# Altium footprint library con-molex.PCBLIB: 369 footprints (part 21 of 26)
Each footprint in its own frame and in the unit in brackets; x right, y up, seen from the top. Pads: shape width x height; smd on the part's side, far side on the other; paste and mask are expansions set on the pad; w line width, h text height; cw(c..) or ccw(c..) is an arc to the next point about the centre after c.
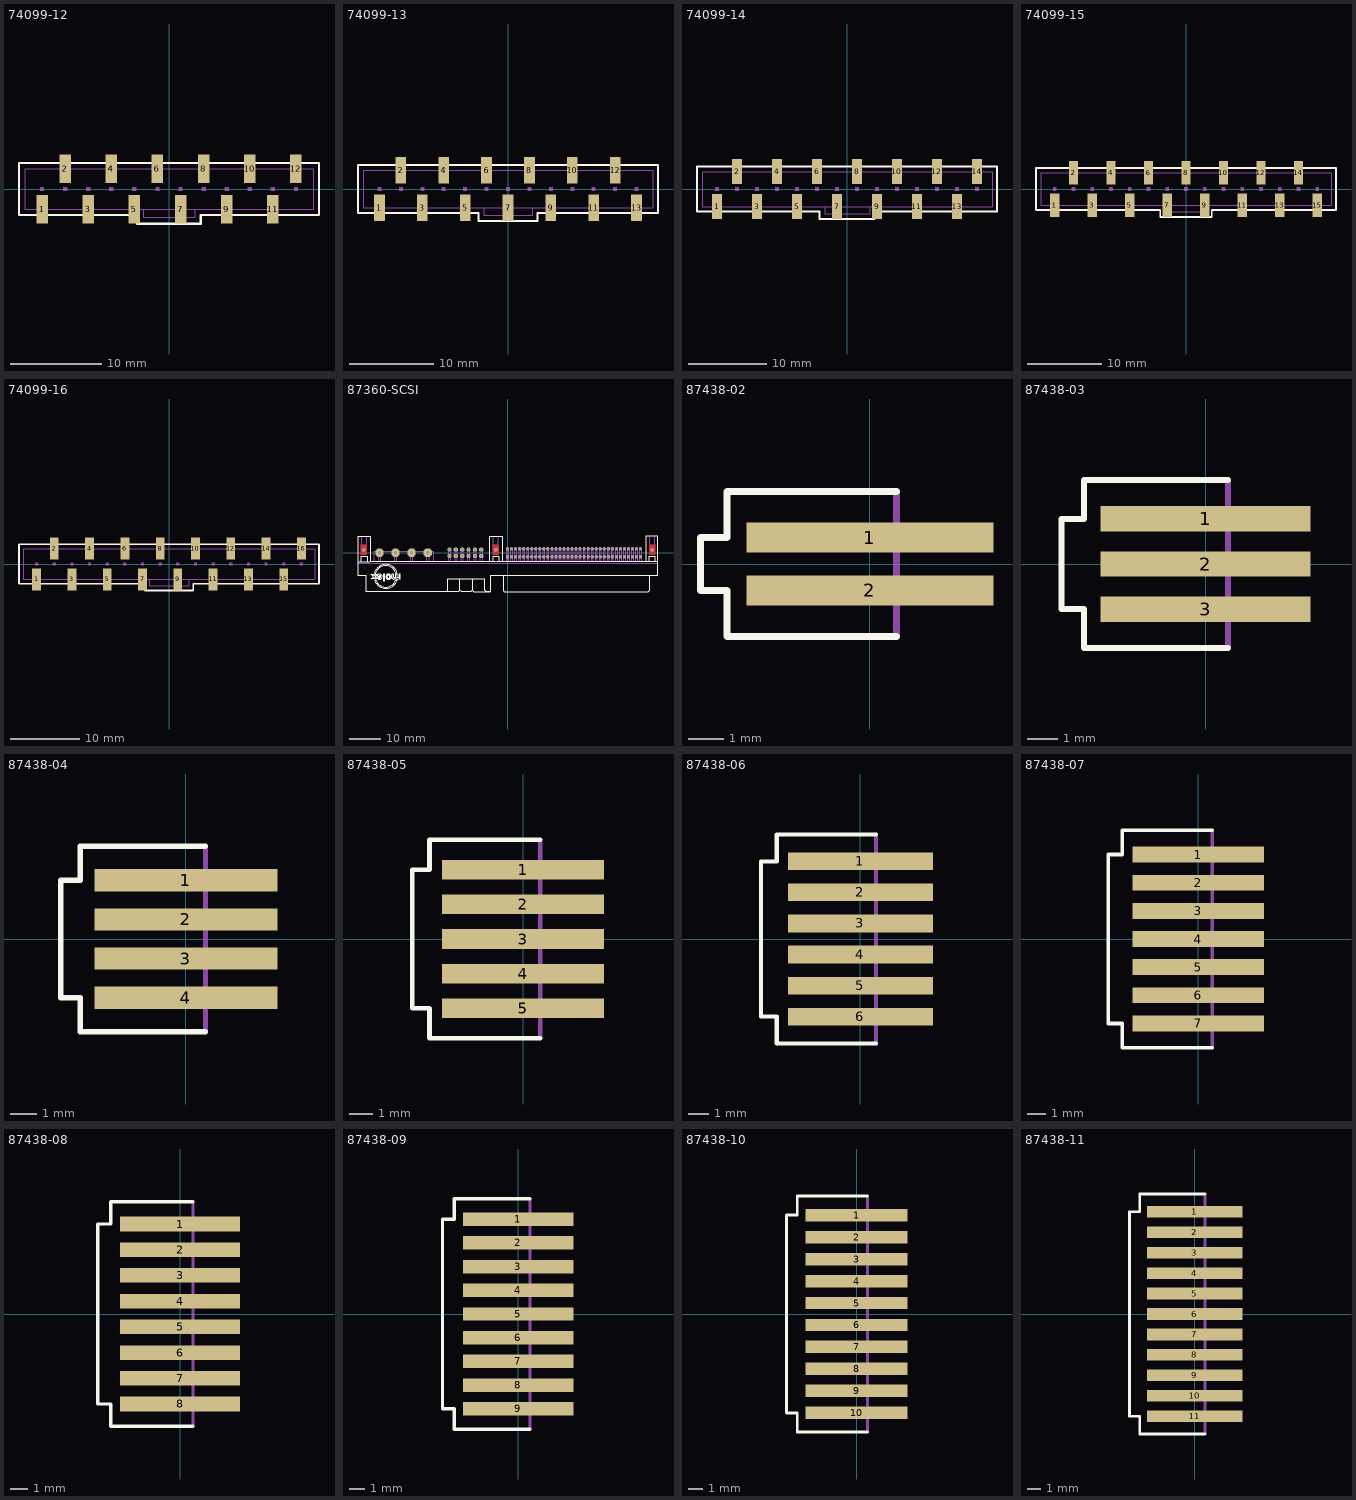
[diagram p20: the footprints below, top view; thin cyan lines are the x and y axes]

## 74099-12 [mil]
pads (12):
  rect 50x125 smd: 1(-550,-87.5) 2(-450,87.5) 3(-350,-87.5) 4(-250,87.5) 5(-150,-87.5) 6(-50,87.5) 7(50,-87.5) 8(150,87.5) 9(250,-87.5) 10(350,87.5) 11(450,-87.5) 12(550,87.5)
Top Overlay:
  lines w10: -650,-112.5 -650,112.5 650,112.5 650,-112.5 137.5,-112.5 137.5,-150 -137.5,-150 -137.5,-112.5 -650,-112.5
Mechanical 16:
  rectangle: -359.37,-9.37 -340.63,9.37
  rectangle: -459.37,-9.37 -440.63,9.37
  rectangle: -159.37,-9.37 -140.63,9.37
  rectangle: -259.37,-9.37 -240.63,9.37
  rectangle: -559.37,-9.37 -540.63,9.37
  rectangle: -59.37,-9.37 -40.63,9.37
  rectangle: 40.63,-9.37 59.37,9.37
  rectangle: 140.63,-9.37 159.37,9.37
  rectangle: 240.63,-9.37 259.37,9.37
  rectangle: 340.63,-9.37 359.37,9.37
  rectangle: 440.63,-9.37 459.37,9.37
  rectangle: 540.63,-9.37 559.37,9.37
  lines w2: -112.5,-87.5 -625,-87.5 -625,87.5 625,87.5 625,-87.5 112.5,-87.5 ; -112.5,-87.5 112.5,-87.5 ; -112.5,-87.5 -112.5,-125 112.5,-125 112.5,-87.5
  text "1" at -612.5,-75 h62

## 74099-13 [mil]
pads (13):
  rect 50x125 smd: 1(-600,-87.5) 2(-500,87.5) 3(-400,-87.5) 4(-300,87.5) 5(-200,-87.5) 6(-100,87.5) 7(0,-87.5) 8(100,87.5) 9(200,-87.5) 10(300,87.5) 11(400,-87.5) 12(500,87.5) 13(600,-87.5)
Top Overlay:
  lines w10: -700,-112.5 -700,112.5 700,112.5 700,-112.5 137.5,-112.5 137.5,-150 -137.5,-150 -137.5,-112.5 -700,-112.5
Mechanical 16:
  rectangle: -409.37,-9.37 -390.63,9.37
  rectangle: -509.37,-9.37 -490.63,9.37
  rectangle: -209.37,-9.37 -190.63,9.37
  rectangle: -309.37,-9.37 -290.63,9.37
  rectangle: -609.37,-9.37 -590.63,9.37
  rectangle: -109.37,-9.37 -90.63,9.37
  rectangle: -9.37,-9.37 9.37,9.37
  rectangle: 90.63,-9.37 109.37,9.37
  rectangle: 190.63,-9.37 209.37,9.37
  rectangle: 290.63,-9.37 309.37,9.37
  rectangle: 390.63,-9.37 409.37,9.37
  rectangle: 490.63,-9.37 509.37,9.37
  rectangle: 590.63,-9.37 609.37,9.37
  lines w2: -112.5,-87.5 -675,-87.5 -675,87.5 675,87.5 675,-87.5 112.5,-87.5 ; -112.5,-87.5 112.5,-87.5 ; -112.5,-87.5 -112.5,-125 112.5,-125 112.5,-87.5
  text "1" at -662.5,-75 h62

## 74099-14 [mil]
pads (14):
  rect 50x125 smd: 1(-650,-87.5) 2(-550,87.5) 3(-450,-87.5) 4(-350,87.5) 5(-250,-87.5) 6(-150,87.5) 7(-50,-87.5) 8(50,87.5) 9(150,-87.5) 10(250,87.5) 11(350,-87.5) 12(450,87.5) 13(550,-87.5) 14(650,87.5)
Top Overlay:
  lines w10: -750,-112.5 -750,112.5 750,112.5 750,-112.5 137.5,-112.5 137.5,-150 -137.5,-150 -137.5,-112.5 -750,-112.5
Mechanical 16:
  rectangle: -459.37,-9.37 -440.63,9.37
  rectangle: -559.37,-9.37 -540.63,9.37
  rectangle: -259.37,-9.37 -240.63,9.37
  rectangle: -359.37,-9.37 -340.63,9.37
  rectangle: -659.37,-9.37 -640.63,9.37
  rectangle: -159.37,-9.37 -140.63,9.37
  rectangle: -59.37,-9.37 -40.63,9.37
  rectangle: 40.63,-9.37 59.37,9.37
  rectangle: 140.63,-9.37 159.37,9.37
  rectangle: 240.63,-9.37 259.37,9.37
  rectangle: 340.63,-9.37 359.37,9.37
  rectangle: 440.63,-9.37 459.37,9.37
  rectangle: 540.63,-9.37 559.37,9.37
  rectangle: 640.63,-9.37 659.37,9.37
  lines w2: -112.5,-87.5 -725,-87.5 -725,87.5 725,87.5 725,-87.5 112.5,-87.5 ; -112.5,-87.5 112.5,-87.5 ; -112.5,-87.5 -112.5,-125 112.5,-125 112.5,-87.5
  text "1" at -712.5,-75 h62

## 74099-15 [mil]
pads (15):
  rect 50x125 smd: 1(-700,-87.5) 2(-600,87.5) 3(-500,-87.5) 4(-400,87.5) 5(-300,-87.5) 6(-200,87.5) 7(-100,-87.5) 8(0,87.5) 9(100,-87.5) 10(200,87.5) 11(300,-87.5) 12(400,87.5) 13(500,-87.5) 14(600,87.5) 15(700,-87.5)
Top Overlay:
  lines w10: -800,-112.5 -800,112.5 800,112.5 800,-112.5 137.5,-112.5 137.5,-150 -137.5,-150 -137.5,-112.5 -800,-112.5
Mechanical 16:
  rectangle: -509.37,-9.37 -490.63,9.37
  rectangle: -609.37,-9.37 -590.63,9.37
  rectangle: -309.37,-9.37 -290.63,9.37
  rectangle: -409.37,-9.37 -390.63,9.37
  rectangle: -709.37,-9.37 -690.63,9.37
  rectangle: -209.37,-9.37 -190.63,9.37
  rectangle: -109.37,-9.37 -90.63,9.37
  rectangle: -9.37,-9.37 9.37,9.37
  rectangle: 90.63,-9.37 109.37,9.37
  rectangle: 190.63,-9.37 209.37,9.37
  rectangle: 290.63,-9.37 309.37,9.37
  rectangle: 390.63,-9.37 409.37,9.37
  rectangle: 490.63,-9.37 509.37,9.37
  rectangle: 590.63,-9.37 609.37,9.37
  rectangle: 690.63,-9.37 709.37,9.37
  lines w2: -112.5,-87.5 -775,-87.5 -775,87.5 775,87.5 775,-87.5 112.5,-87.5 ; -112.5,-87.5 112.5,-87.5 ; -112.5,-87.5 -112.5,-125 112.5,-125 112.5,-87.5
  text "1" at -762.5,-75 h62

## 74099-16 [mil]
pads (16):
  rect 50x125 smd: 1(-750,-87.5) 2(-650,87.5) 3(-550,-87.5) 4(-450,87.5) 5(-350,-87.5) 6(-250,87.5) 7(-150,-87.5) 8(-50,87.5) 9(50,-87.5) 10(150,87.5) 11(250,-87.5) 12(350,87.5) 13(450,-87.5) 14(550,87.5) 15(650,-87.5) 16(750,87.5)
Top Overlay:
  lines w10: -850,-112.5 -850,112.5 850,112.5 850,-112.5 137.5,-112.5 137.5,-150 -137.5,-150 -137.5,-112.5 -850,-112.5
Mechanical 16:
  rectangle: -559.37,-9.37 -540.63,9.37
  rectangle: -659.37,-9.37 -640.63,9.37
  rectangle: -359.37,-9.37 -340.63,9.37
  rectangle: -459.37,-9.37 -440.63,9.37
  rectangle: -759.37,-9.37 -740.63,9.37
  rectangle: -259.37,-9.37 -240.63,9.37
  rectangle: -159.37,-9.37 -140.63,9.37
  rectangle: -59.37,-9.37 -40.63,9.37
  rectangle: 40.63,-9.37 59.37,9.37
  rectangle: 140.63,-9.37 159.37,9.37
  rectangle: 240.63,-9.37 259.37,9.37
  rectangle: 340.63,-9.37 359.37,9.37
  rectangle: 440.63,-9.37 459.37,9.37
  rectangle: 540.63,-9.37 559.37,9.37
  rectangle: 640.63,-9.37 659.37,9.37
  rectangle: 740.63,-9.37 759.37,9.37
  lines w2: -112.5,-87.5 -825,-87.5 -825,87.5 825,87.5 825,-87.5 112.5,-87.5 ; -112.5,-87.5 112.5,-87.5 ; -112.5,-87.5 -112.5,-125 112.5,-125 112.5,-87.5
  text "1" at -812.5,-75 h62

## 87360-SCSI [mil]
pads (87):
  round 44.88 hole 44.88: 1(-1783.27,36.22) 1(-145.08,36.22) 1(1795.08,36.22)
  oct 40x40 hole 27.56: 1(0,50) 2(50,50) 3(100,50) 4(150,50) 5(200,50) 6(250,50) 7(300,50) 8(350,50) 9(400,50) 10(450,50) 11(500,50) 12(550,50) 13(600,50) 14(650,50) 15(700,50) 16(750,50) 17(800,50) 18(850,50) 19(900,50) 20(950,50) 21(1000,50) 22(1050,50) 23(1100,50) 24(1150,50) 25(1200,50) 26(1250,50) 27(1300,50) 28(1350,50) 29(1400,50) 30(1450,50) 31(1500,50) 32(1550,50) 33(1600,50) 34(1650,50) 35(0,-50) 36(50,-50) 37(100,-50) 38(150,-50) 39(200,-50) 40(250,-50) 41(300,-50) 42(350,-50) 43(400,-50) 44(450,-50) 45(500,-50) 46(550,-50) 47(600,-50) 48(650,-50) 49(700,-50) 50(750,-50) 51(800,-50) 52(850,-50) 53(900,-50) 54(950,-50) 55(1000,-50) 56(1050,-50) 57(1100,-50) 58(1150,-50) 59(1200,-50) 60(1250,-50) 61(1300,-50) 62(1350,-50) 63(1400,-50) 64(1450,-50) 65(1500,-50) 66(1550,-50) 67(1600,-50) 68(1650,-50)
  oct 53.15x53.15 hole 35.43: J1(-719.69,39.37) J2(-719.69,-39.37) J3(-640.94,39.37) J4(-640.94,-39.37) J5(-562.2,39.37) J6(-562.2,-39.37) J7(-483.46,39.37) J8(-483.46,-39.37) J9(-404.72,39.37) J10(-404.72,-39.37) J11(-325.98,39.37) J12(-325.98,-39.37)
  oct 100x100 hole 39.37: P1(-1589.76,0) P2(-1389.76,0) P3(-1189.76,0) P4(-989.76,0)
Top Layer:
  rectangle: -1823.23,-26.57 -1743.5,99.41
  rectangle: -184.45,-26.57 -105.71,99.41
  rectangle: 1755.51,-26.57 1834.25,99.41
Bottom Layer:
  rectangle: -1823.23,-26.57 -1743.5,99.41
  rectangle: -184.45,-26.57 -105.71,99.41
  rectangle: 1755.51,-26.57 1834.25,99.41
Top Overlay:
  circle w8: c-1476.94,-297.65 r33.91
  circle w8: c-1476.94,-297.65 r18.84
  lines w8: -1854.33,-130.59 -1854.33,-287.4 ; -1850.39,-110.24 -1708.66,-110.24 ; -1814.96,-106.3 -1814.96,-43.31 -1740.16,-43.31 -1740.16,-106.3 ; -1638.98,-256.22 -1654.02,-256.22 cw(c-1510.32,-293.9) -1367.67,-252.45 ; -1638.96,-259.97 cw(c-1510.86,-293.88) -1382.75,-259.97 ; -1616.34,-293.9 -1571.14,-293.9 -1571.14,-286.34 -1574.92,-282.6 -1593.74,-282.6 -1601.3,-290.12 ; -1397.83,-312.72 -1409.13,-312.72 -1412.91,-308.94 -1412.91,-267.52 -1435.51,-267.52 -1435.51,-312.72 -1420.43,-327.8 -1405.35,-327.8 -1394.06,-316.5 ; -1386.54,-342.87 -1371.46,-342.87 cw(c-1510.23,-293.88) -1650.28,-339.09 -1635.2,-339.09 ccw(c-1510.87,-293.88) -1386.53,-339.09 ; -1382.76,-256.22 -1367.68,-256.22 ; -1356.38,-312.72 -1367.68,-312.72 -1371.46,-308.94 -1371.46,-267.52 -1394.06,-267.52 -1394.06,-312.72 -1378.98,-327.8 -1360.16,-327.8 -1352.6,-320.28 ; -609.13,-484.25 -610.24,-484.25 ; -588.62,-326.77 -439.84,-326.77 ; -456.69,-484.25 -437.01,-464.57 ; -455,-484.25 -570.87,-484.25 -590.55,-464.57 ; -417.32,-484.25 -437.01,-464.57 ; -416.85,-484.25 -212.6,-484.25 ; -181.1,-110.24 -220.47,-110.24 ; -102.36,-110.24 -66.93,-110.24 ; 1718.98,-110.24 1863.46,-110.24 ; 1866.14,-130.59 1866.14,-287.4 ; 1866.14,196.85 1866.14,204.72 ; -1854.33,-287.4 -1755.91,-287.4 ; -1854.33,-287.4 -1755.91,-287.4 ; -1854.33,-287.4 -1854.33,204.72 -1700.79,204.72 -1700.79,-110.24 -220.47,-110.24 ; -1755.91,-484.25 -1755.91,-287.4 ; -1755.91,-484.25 -759.84,-484.25 -748.03,-472.44 -748.03,-326.77 -590.55,-326.77 ; -1755.91,-484.25 -1755.91,-287.4 ; -1755.91,-484.25 -610.24,-484.25 ; -610.24,-484.25 -590.55,-464.57 ; -590.55,-464.57 -590.55,-326.77 ; -590.55,-464.57 -590.55,-326.77 ; -437.01,-464.57 -437.01,-326.77 ; -437.01,-464.57 -437.01,-326.77 ; -437.01,-326.77 -283.46,-326.77 -283.46,-464.57 -263.78,-484.25 -212.6,-484.25 ; -220.47,-110.24 -220.47,204.72 -66.93,204.72 -66.93,-110.24 ; -212.6,-484.25 -212.6,-287.4 ; -212.6,-484.25 -212.6,-287.4 ; -212.6,-287.4 -55.12,-287.4 ; -212.6,-287.4 -55.12,-287.4 ; -66.93,-110.24 1716.54,-110.24 1716.54,204.72 1866.14,204.72 ; -55.12,-468.5 -55.12,-287.4 ; -55.12,-468.5 -39.37,-484.25 ; -55.12,-468.5 -55.12,-287.4 ; -55.12,-468.5 -39.37,-484.25 ; -55.12,-287.4 1755.91,-287.4 ; -55.12,-287.4 1755.91,-287.4 ; -39.37,-484.25 1744.09,-484.25 ; -39.37,-484.25 1744.09,-484.25 ; 1744.09,-484.25 1755.91,-472.44 ; 1744.09,-484.25 1755.91,-472.44 ; 1755.91,-472.44 1755.91,-287.4 ; 1755.91,-472.44 1755.91,-287.4 ; 1755.91,-287.4 1866.14,-287.4 ; 1755.91,-287.4 1866.14,-287.4 ; 1866.14,-287.4 1866.14,204.72 ; -1691.69,-267.52 -1669.09,-267.52 -1654.02,-282.6 -1638.98,-267.52 -1616.34,-267.52 -1642.72,-293.9 -1642.72,-301.42 -1620.12,-324.02 -1642.72,-324.02 -1654.02,-312.72 -1665.31,-324.02 -1687.95,-324.02 -1665.31,-301.42 -1665.31,-293.9 -1691.69,-267.52 ; -1620.12,-301.42 -1620.12,-286.34 -1601.3,-267.52 -1571.14,-267.52 -1556.06,-282.6 -1556.06,-305.2 -1559.84,-316.5 -1574.92,-327.8 -1597.52,-327.8 -1616.34,-312.72 -1620.12,-301.42 ; -1601.3,-305.2 -1571.14,-305.2 -1582.44,-316.5 -1589.96,-316.5 -1601.3,-305.2 ; -1544.76,-350.39 -1544.76,-267.52 -1525.94,-267.52 -1525.94,-350.39 -1544.76,-350.39 ; -1352.6,-316.5 -1352.6,-267.52 -1330,-267.52 -1330,-324.02 -1345.08,-324.02 -1352.6,-316.5 ; -177.17,-110.24 -106.3,-110.24 -106.3,-43.31 -177.17,-43.31 -177.17,-110.24 ; 1755.91,-110.24 1826.77,-110.24 1826.77,-43.31 1755.91,-43.31 1755.91,-110.24
Mechanical 1:
  lines w0: -1855.28,-128.74 1866.3,-128.74
Mechanical 16:
  drawing of 156 lines, arcs and shapes, not listed

## 87438-02 [mm]
pads (2):
  rect 7x0.85 smd: 1(0,0.75) 2(0,-0.75)
Top Overlay:
  lines w0.203: 0.75,-2.05 -4.05,-2.05 -4.05,-0.75 -4.8,-0.75 -4.8,0.75 -4.05,0.75 -4.05,2.05 0.75,2.05
Mechanical 16:
  rectangle: 0.8,0.525 2.85,0.975
  rectangle: 0.8,-0.975 2.85,-0.525
  lines w0.203: 0.75,-2.05 0.75,2.05

## 87438-03 [mm]
pads (3):
  rect 7x0.85 smd: 1(0,1.5) 2(0,0) 3(0,-1.5)
Top Overlay:
  lines w0.203: 0.75,-2.8 -4.05,-2.8 -4.05,-1.5 -4.8,-1.5 -4.8,1.5 -4.05,1.5 -4.05,2.8 0.75,2.8
Mechanical 16:
  rectangle: 0.8,1.275 2.85,1.725
  rectangle: 0.8,-0.225 2.85,0.225
  rectangle: 0.8,-1.725 2.85,-1.275
  lines w0.203: 0.75,-2.8 0.75,2.8

## 87438-04 [mm]
pads (4):
  rect 7x0.85 smd: 1(0,2.25) 2(0,0.75) 3(0,-0.75) 4(0,-2.25)
Top Overlay:
  lines w0.203: 0.75,-3.55 -4.05,-3.55 -4.05,-2.25 -4.8,-2.25 -4.8,2.25 -4.05,2.25 -4.05,3.55 0.75,3.55
Mechanical 16:
  rectangle: 0.8,2.025 2.85,2.475
  rectangle: 0.8,0.525 2.85,0.975
  rectangle: 0.8,-0.975 2.85,-0.525
  rectangle: 0.8,-2.475 2.85,-2.025
  lines w0.203: 0.75,-3.55 0.75,3.55

## 87438-05 [mm]
pads (5):
  rect 7x0.85 smd: 1(0,3) 2(0,1.5) 3(0,0) 4(0,-1.5) 5(0,-3)
Top Overlay:
  lines w0.203: 0.75,-4.3 -4.05,-4.3 -4.05,-3 -4.8,-3 -4.8,3 -4.05,3 -4.05,4.3 0.75,4.3
Mechanical 16:
  rectangle: 0.8,2.775 2.85,3.225
  rectangle: 0.8,1.275 2.85,1.725
  rectangle: 0.8,-0.225 2.85,0.225
  rectangle: 0.8,-1.725 2.85,-1.275
  rectangle: 0.8,-3.225 2.85,-2.775
  lines w0.203: 0.75,-4.3 0.75,4.3

## 87438-06 [mm]
pads (6):
  rect 7x0.85 smd: 1(0,3.75) 2(0,2.25) 3(0,0.75) 4(0,-0.75) 5(0,-2.25) 6(0,-3.75)
Top Overlay:
  lines w0.203: 0.75,-5.05 -4.05,-5.05 -4.05,-3.75 -4.8,-3.75 -4.8,3.75 -4.05,3.75 -4.05,5.05 0.75,5.05
Mechanical 16:
  rectangle: 0.8,3.525 2.85,3.975
  rectangle: 0.8,2.025 2.85,2.475
  rectangle: 0.8,0.525 2.85,0.975
  rectangle: 0.8,-0.975 2.85,-0.525
  rectangle: 0.8,-2.475 2.85,-2.025
  rectangle: 0.8,-3.975 2.85,-3.525
  lines w0.203: 0.75,-5.05 0.75,5.05

## 87438-07 [mm]
pads (7):
  rect 7x0.85 smd: 1(0,4.5) 2(0,3) 3(0,1.5) 4(0,0) 5(0,-1.5) 6(0,-3) 7(0,-4.5)
Top Overlay:
  lines w0.203: 0.75,-5.8 -4.05,-5.8 -4.05,-4.5 -4.8,-4.5 -4.8,4.5 -4.05,4.5 -4.05,5.8 0.75,5.8
Mechanical 16:
  rectangle: 0.8,4.275 2.85,4.725
  rectangle: 0.8,2.775 2.85,3.225
  rectangle: 0.8,1.275 2.85,1.725
  rectangle: 0.8,-0.225 2.85,0.225
  rectangle: 0.8,-1.725 2.85,-1.275
  rectangle: 0.8,-3.225 2.85,-2.775
  rectangle: 0.8,-4.725 2.85,-4.275
  lines w0.203: 0.75,-5.8 0.75,5.8

## 87438-08 [mm]
pads (8):
  rect 7x0.85 smd: 1(0,5.25) 2(0,3.75) 3(0,2.25) 4(0,0.75) 5(0,-0.75) 6(0,-2.25) 7(0,-3.75) 8(0,-5.25)
Top Overlay:
  lines w0.203: 0.75,-6.55 -4.05,-6.55 -4.05,-5.25 -4.8,-5.25 -4.8,5.25 -4.05,5.25 -4.05,6.55 0.75,6.55
Mechanical 16:
  rectangle: 0.8,5.025 2.85,5.475
  rectangle: 0.8,3.525 2.85,3.975
  rectangle: 0.8,2.025 2.85,2.475
  rectangle: 0.8,0.525 2.85,0.975
  rectangle: 0.8,-0.975 2.85,-0.525
  rectangle: 0.8,-2.475 2.85,-2.025
  rectangle: 0.8,-3.975 2.85,-3.525
  rectangle: 0.8,-5.475 2.85,-5.025
  lines w0.203: 0.75,-6.55 0.75,6.55

## 87438-09 [mm]
pads (9):
  rect 7x0.85 smd: 1(0,6) 2(0,4.5) 3(0,3) 4(0,1.5) 5(0,0) 6(0,-1.5) 7(0,-3) 8(0,-4.5) 9(0,-6)
Top Overlay:
  lines w0.203: 0.75,-7.3 -4.05,-7.3 -4.05,-6 -4.8,-6 -4.8,6 -4.05,6 -4.05,7.3 0.75,7.3
Mechanical 16:
  rectangle: 0.8,5.775 2.85,6.225
  rectangle: 0.8,4.275 2.85,4.725
  rectangle: 0.8,2.775 2.85,3.225
  rectangle: 0.8,1.275 2.85,1.725
  rectangle: 0.8,-0.225 2.85,0.225
  rectangle: 0.8,-1.725 2.85,-1.275
  rectangle: 0.8,-3.225 2.85,-2.775
  rectangle: 0.8,-4.725 2.85,-4.275
  rectangle: 0.8,-6.225 2.85,-5.775
  lines w0.203: 0.75,-7.3 0.75,7.3

## 87438-10 [mm]
pads (10):
  rect 7x0.85 smd: 1(0,6.75) 2(0,5.25) 3(0,3.75) 4(0,2.25) 5(0,0.75) 6(0,-0.75) 7(0,-2.25) 8(0,-3.75) 9(0,-5.25) 10(0,-6.75)
Top Overlay:
  lines w0.203: 0.75,-8.05 -4.05,-8.05 -4.05,-6.75 -4.8,-6.75 -4.8,6.75 -4.05,6.75 -4.05,8.05 0.75,8.05
Mechanical 16:
  rectangle: 0.8,6.525 2.85,6.975
  rectangle: 0.8,5.025 2.85,5.475
  rectangle: 0.8,3.525 2.85,3.975
  rectangle: 0.8,2.025 2.85,2.475
  rectangle: 0.8,0.525 2.85,0.975
  rectangle: 0.8,-0.975 2.85,-0.525
  rectangle: 0.8,-2.475 2.85,-2.025
  rectangle: 0.8,-3.975 2.85,-3.525
  rectangle: 0.8,-5.475 2.85,-5.025
  rectangle: 0.8,-6.975 2.85,-6.525
  lines w0.203: 0.75,-8.05 0.75,8.05

## 87438-11 [mm]
pads (11):
  rect 7x0.85 smd: 1(0,7.5) 2(0,6) 3(0,4.5) 4(0,3) 5(0,1.5) 6(0,0) 7(0,-1.5) 8(0,-3) 9(0,-4.5) 10(0,-6) 11(0,-7.5)
Top Overlay:
  lines w0.203: 0.75,-8.8 -4.05,-8.8 -4.05,-7.5 -4.8,-7.5 -4.8,7.5 -4.05,7.5 -4.05,8.8 0.75,8.8
Mechanical 16:
  rectangle: 0.8,7.275 2.85,7.725
  rectangle: 0.8,5.775 2.85,6.225
  rectangle: 0.8,4.275 2.85,4.725
  rectangle: 0.8,2.775 2.85,3.225
  rectangle: 0.8,1.275 2.85,1.725
  rectangle: 0.8,-0.225 2.85,0.225
  rectangle: 0.8,-1.725 2.85,-1.275
  rectangle: 0.8,-3.225 2.85,-2.775
  rectangle: 0.8,-4.725 2.85,-4.275
  rectangle: 0.8,-6.225 2.85,-5.775
  rectangle: 0.8,-7.725 2.85,-7.275
  lines w0.203: 0.75,-8.8 0.75,8.8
